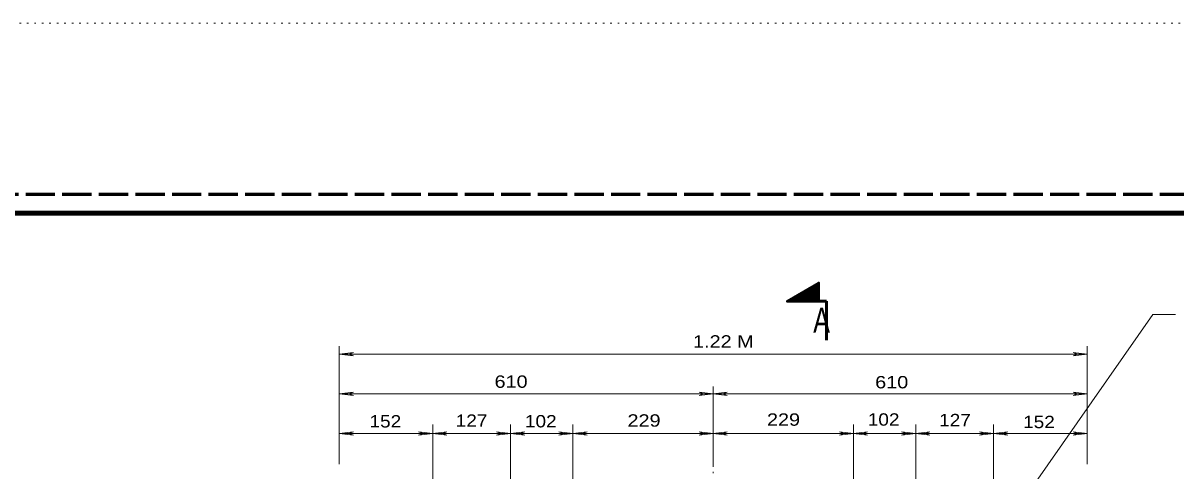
# Model space of a CAD drawing. Extents: x 312583 to 312854, y 144419 to 144597.
# Drawn here: x 312620.3 to 312691.2, y 144569.2 to 144596.8 of the extents above; entities that cross this region are included whole.
import ezdxf
from ezdxf.enums import TextEntityAlignment as Align

# ---------------------------------------------------------------- set-up
doc = ezdxf.new("R2010")
doc.units = 0
doc.header["$LTSCALE"] = 0.3
doc.linetypes.add('DOTTED', pattern=[1.5, 0.3, -1.2])
doc.linetypes.add('LONG_DASHED', pattern=[7.5, 6, -1.5])
for name, color, linetype, lineweight in [('1', 7, 'Continuous', 25), ('2', 7, 'Continuous', 13), ('63', 7, 'DOTTED', 13)]:
    doc.layers.add(name, color=color, linetype=linetype, lineweight=lineweight)

msp = doc.modelspace()

# ---------------------------------------------------------------- linework, layer by layer
at = {"layer": '1', "linetype": 'LONG_DASHED', "lineweight": 60}
msp.add_line((312851.75, 144586.2246), (312583.526, 144586.2246), dxfattribs=at)
at = {"layer": '1', "lineweight": 35}
for p, q in [((312668.867, 144579.6636), (312668.476, 144580.3383)), ((312668.8977, 144579.6636), (312668.499, 144580.3536)), ((312668.9284, 144579.6636), (312668.522, 144580.369)), ((312668.9514, 144579.6636), (312668.545, 144580.3766)), ((312668.982, 144579.6636), (312668.5604, 144580.392)), ((312669.0127, 144579.6636), (312668.5834, 144580.4073)), ((312669.0357, 144579.6713), (312668.6064, 144580.415)), ((312669.0664, 144579.6713), (312668.6217, 144580.4303)), ((312669.0894, 144579.6636), (312668.6447, 144580.438)), ((312669.12, 144579.6636), (312668.6677, 144580.4533)), ((312669.143, 144579.6636), (312668.683, 144580.461)), ((312669.1737, 144579.6636), (312668.706, 144580.4763)), ((312669.2044, 144579.6636), (312668.729, 144580.484)), ((312669.2197, 144579.6866), (312668.7444, 144580.4993)), ((312669.2197, 144579.7403), (312668.775, 144580.507)), ((312669.2197, 144579.7786), (312668.7904, 144580.5223)), ((312669.2197, 144579.8323), (312668.8134, 144580.53)), ((312669.2197, 144579.8783), (312668.8364, 144580.5453)), ((312669.2197, 144579.9243), (312668.8517, 144580.5606)), ((312669.2197, 144579.9703), (312668.8747, 144580.5683)), ((312669.2197, 144580.024), (312668.8977, 144580.5836)), ((312669.2197, 144580.07), (312668.913, 144580.599)), ((312669.2197, 144580.116), (312668.936, 144580.6066)), ((312669.2197, 144580.1696), (312668.9514, 144580.622)), ((312669.2197, 144580.2156), (312668.9744, 144580.6296)), ((312669.2197, 144580.2616), (312668.9974, 144580.645)), ((312669.2197, 144580.3153), (312669.0127, 144580.6526)), ((312669.2197, 144580.3613), (312669.0434, 144580.668)), ((312669.2197, 144580.4073), (312669.0587, 144580.6756)), ((312669.2197, 144580.4533), (312669.0817, 144580.691)), ((312669.2197, 144580.507), (312669.1047, 144580.6986)), ((312669.2197, 144580.5453), (312669.12, 144580.714)), ((312669.2197, 144580.599), (312669.143, 144580.7216)), ((312669.2197, 144580.645), (312669.166, 144580.737)), ((312669.2197, 144580.6986), (312669.1814, 144580.7523)), ((312669.2197, 144580.7446), (312669.2044, 144580.76)), ((312667.3184, 144579.6636), (312667.3184, 144579.679)), ((312667.349, 144579.6636), (312667.3414, 144579.6866)), ((312667.3797, 144579.6636), (312667.3567, 144579.702)), ((312667.4027, 144579.6636), (312667.3797, 144579.7096)), ((312667.4334, 144579.6636), (312667.4027, 144579.725)), ((312667.4564, 144579.6636), (312667.418, 144579.7326)), ((312667.487, 144579.6636), (312667.441, 144579.748)), ((312667.5177, 144579.6636), (312667.464, 144579.7556)), ((312667.5484, 144579.6636), (312667.4794, 144579.771)), ((312667.5714, 144579.6636), (312667.5024, 144579.7786)), ((312667.5944, 144579.6636), (312667.5254, 144579.794)), ((312667.625, 144579.6636), (312667.5484, 144579.8016)), ((312667.648, 144579.6636), (312667.5637, 144579.817)), ((312667.6787, 144579.6636), (312667.5867, 144579.8323)), ((312667.7094, 144579.6636), (312667.6097, 144579.84)), ((312667.74, 144579.6636), (312667.625, 144579.8553)), ((312667.763, 144579.6636), (312667.648, 144579.8706)), ((312667.7937, 144579.6636), (312667.671, 144579.8783)), ((312667.8167, 144579.6636), (312667.6864, 144579.8936)), ((312667.8474, 144579.6636), (312667.7094, 144579.9013)), ((312667.878, 144579.6636), (312667.7324, 144579.9166)), ((312667.901, 144579.6636), (312667.7477, 144579.9243)), ((312667.9317, 144579.6636), (312667.7784, 144579.9396)), ((312667.9547, 144579.6636), (312667.7937, 144579.9473)), ((312667.9854, 144579.6636), (312667.8167, 144579.9626)), ((312668.016, 144579.6636), (312667.8397, 144579.9703)), ((312668.039, 144579.6636), (312667.855, 144579.9856)), ((312668.0697, 144579.6636), (312667.878, 144579.9933)), ((312668.0927, 144579.6636), (312667.901, 144580.0086)), ((312668.1234, 144579.6636), (312667.9164, 144580.024)), ((312668.1464, 144579.6636), (312667.9394, 144580.0316)), ((312668.177, 144579.6636), (312667.9624, 144580.047)), ((312668.2077, 144579.6636), (312667.9777, 144580.0623)), ((312668.2384, 144579.6636), (312668.0007, 144580.07)), ((312668.2614, 144579.6636), (312668.0237, 144580.0853)), ((312668.2844, 144579.6636), (312668.0467, 144580.093)), ((312668.315, 144579.6636), (312668.062, 144580.1083)), ((312668.3457, 144579.6636), (312668.085, 144580.116)), ((312668.3687, 144579.6636), (312668.108, 144580.1313)), ((312668.3994, 144579.6636), (312668.1234, 144580.139)), ((312668.43, 144579.6636), (312668.1464, 144580.1543)), ((312668.453, 144579.6636), (312668.1694, 144580.162)), ((312668.4837, 144579.6636), (312668.1847, 144580.1773)), ((312668.5144, 144579.6636), (312668.2077, 144580.185)), ((312668.5374, 144579.6636), (312668.2307, 144580.2003)), ((312668.568, 144579.6713), (312668.246, 144580.2156)), ((312668.591, 144579.6636), (312668.2767, 144580.2233)), ((312668.6217, 144579.6636), (312668.292, 144580.2386)), ((312668.6447, 144579.6636), (312668.315, 144580.2463)), ((312668.6754, 144579.6636), (312668.338, 144580.2616)), ((312668.706, 144579.6636), (312668.3534, 144580.2693)), ((312668.7367, 144579.6636), (312668.3764, 144580.2846)), ((312668.7597, 144579.6636), (312668.3994, 144580.2923)), ((312668.7827, 144579.6636), (312668.4147, 144580.3076)), ((312668.8134, 144579.6713), (312668.4377, 144580.3153)), ((312668.844, 144579.6636), (312668.4607, 144580.3306))]:
    msp.add_line(p, q, dxfattribs=at)
at = {"layer": '1', "lineweight": 53}
for p in [(312669.2197, 144579.6636), (312669.695, 144577.2716)]:
    msp.add_line(p, (312669.695, 144579.6636), dxfattribs=at)
at = {"layer": '1', "lineweight": 158}
msp.add_lwpolyline([(312616.5, 144423.1446), (312616.5, 144585.0846), (312849, 144585.0846)], dxfattribs=at)
at = {"layer": '1', "lineweight": 53}
msp.add_lwpolyline([(312669.2197, 144579.6636), (312669.2197, 144580.7753), (312667.303, 144579.6636)], close=True, dxfattribs=at)
at = {"layer": '2'}
for p, q in [((312639.7337, 144569.628), (312639.7337, 144576.8883)), ((312685.7337, 144569.628), (312685.7337, 144576.8883)), ((312639.7337, 144576.3976), (312640.6, 144576.505)), ((312639.7337, 144576.3976), (312685.7337, 144576.3976)), ((312639.7337, 144576.3976), (312640.6, 144576.2903)), ((312640.6, 144576.505), (312640.324, 144576.3976)), ((312640.6, 144576.2903), (312640.324, 144576.3976)), ((312684.8674, 144576.505), (312685.1434, 144576.3976)), ((312685.7337, 144576.3976), (312684.8674, 144576.505)), ((312684.8674, 144576.2903), (312685.1434, 144576.3976)), ((312685.7337, 144576.3976), (312684.8674, 144576.2903)), ((312639.7337, 144573.9596), (312640.6, 144574.067)), ((312639.7337, 144573.9596), (312640.6, 144573.8523)), ((312640.6, 144574.067), (312640.324, 144573.9596)), ((312640.6, 144573.8523), (312640.324, 144573.9596)), ((312661.8674, 144574.067), (312662.1434, 144573.9596)), ((312662.7337, 144573.9596), (312661.8674, 144574.067)), ((312661.8674, 144573.8523), (312662.1434, 144573.9596)), ((312662.7337, 144573.9596), (312661.8674, 144573.8523)), ((312662.7337, 144569.4746), (312662.7337, 144574.4043)), ((312662.7337, 144573.9596), (312663.6, 144574.067)), ((312662.7337, 144573.9596), (312663.6, 144573.8523)), ((312663.6, 144574.067), (312663.324, 144573.9596)), ((312663.6, 144573.8523), (312663.324, 144573.9596)), ((312684.8674, 144574.067), (312685.1434, 144573.9596)), ((312685.7337, 144573.9596), (312684.8674, 144574.067)), ((312684.8674, 144573.8523), (312685.1434, 144573.9596)), ((312685.7337, 144573.9596), (312684.8674, 144573.8523)), ((312645.4837, 144566.5843), (312645.4837, 144572.0813)), ((312650.2754, 144567.972), (312650.2754, 144572.0813)), ((312654.1087, 144566.5843), (312654.1087, 144572.0813)), ((312671.3587, 144566.5843), (312671.3587, 144572.0813)), ((312675.192, 144567.972), (312675.192, 144572.0813)), ((312679.9837, 144567.972), (312679.9837, 144572.0813)), ((312639.7337, 144571.5216), (312640.6, 144571.629)), ((312639.7337, 144571.5216), (312640.6, 144571.4143)), ((312640.6, 144571.629), (312640.324, 144571.5216)), ((312640.6, 144571.4143), (312640.324, 144571.5216)), ((312644.6174, 144571.629), (312644.8934, 144571.5216)), ((312645.4837, 144571.5216), (312644.6174, 144571.629)), ((312644.6174, 144571.4143), (312644.8934, 144571.5216)), ((312645.4837, 144571.5216), (312644.6174, 144571.4143)), ((312645.4837, 144571.5216), (312646.35, 144571.629)), ((312645.4837, 144571.5216), (312646.35, 144571.4143)), ((312646.35, 144571.629), (312646.074, 144571.5216)), ((312646.35, 144571.4143), (312646.074, 144571.5216)), ((312649.409, 144571.629), (312649.685, 144571.5216)), ((312650.2754, 144571.5216), (312649.409, 144571.629)), ((312649.409, 144571.4143), (312649.685, 144571.5216)), ((312650.2754, 144571.5216), (312649.409, 144571.4143)), ((312650.2754, 144571.5216), (312651.1417, 144571.629)), ((312650.2754, 144571.5216), (312651.1417, 144571.4143)), ((312651.1417, 144571.629), (312650.8657, 144571.5216)), ((312651.1417, 144571.4143), (312650.8657, 144571.5216)), ((312653.2424, 144571.629), (312653.5184, 144571.5216)), ((312654.1087, 144571.5216), (312653.2424, 144571.629)), ((312653.2424, 144571.4143), (312653.5184, 144571.5216)), ((312654.1087, 144571.5216), (312653.2424, 144571.4143)), ((312654.1087, 144571.5216), (312654.975, 144571.629)), ((312654.1087, 144571.5216), (312654.975, 144571.4143)), ((312654.975, 144571.629), (312654.699, 144571.5216)), ((312654.975, 144571.4143), (312654.699, 144571.5216)), ((312661.8674, 144571.629), (312662.1434, 144571.5216)), ((312662.7337, 144571.5216), (312661.8674, 144571.629)), ((312661.8674, 144571.4143), (312662.1434, 144571.5216)), ((312662.7337, 144571.5216), (312661.8674, 144571.4143)), ((312662.7337, 144571.5216), (312663.6, 144571.629)), ((312662.7337, 144571.5216), (312663.6, 144571.4143)), ((312663.6, 144571.629), (312663.324, 144571.5216)), ((312663.6, 144571.4143), (312663.324, 144571.5216)), ((312670.4924, 144571.629), (312670.7684, 144571.5216)), ((312671.3587, 144571.5216), (312670.4924, 144571.629)), ((312670.4924, 144571.4143), (312670.7684, 144571.5216)), ((312671.3587, 144571.5216), (312670.4924, 144571.4143)), ((312671.3587, 144571.5216), (312672.225, 144571.629)), ((312671.3587, 144571.5216), (312672.225, 144571.4143)), ((312672.225, 144571.629), (312671.949, 144571.5216)), ((312672.225, 144571.4143), (312671.949, 144571.5216)), ((312674.3257, 144571.629), (312674.6017, 144571.5216)), ((312675.192, 144571.5216), (312674.3257, 144571.629)), ((312674.3257, 144571.4143), (312674.6017, 144571.5216)), ((312675.192, 144571.5216), (312674.3257, 144571.4143)), ((312675.192, 144571.5216), (312676.0584, 144571.629)), ((312675.192, 144571.5216), (312676.0584, 144571.4143)), ((312676.0584, 144571.629), (312675.7824, 144571.5216)), ((312676.0584, 144571.4143), (312675.7824, 144571.5216)), ((312679.1174, 144571.629), (312679.3934, 144571.5216)), ((312679.9837, 144571.5216), (312679.1174, 144571.629)), ((312679.1174, 144571.4143), (312679.3934, 144571.5216)), ((312679.9837, 144571.5216), (312679.1174, 144571.4143)), ((312679.9837, 144571.5216), (312680.85, 144571.629)), ((312679.9837, 144571.5216), (312680.85, 144571.4143)), ((312680.85, 144571.629), (312680.574, 144571.5216)), ((312680.85, 144571.4143), (312680.574, 144571.5216)), ((312684.8674, 144571.629), (312685.1434, 144571.5216)), ((312685.7337, 144571.5216), (312684.8674, 144571.629)), ((312684.8674, 144571.4143), (312685.1434, 144571.5216)), ((312685.7337, 144571.5216), (312684.8674, 144571.4143))]:
    msp.add_line(p, q, dxfattribs=at)
at = {"layer": '2', "linetype": 'DOTTED'}
msp.add_line((312662.7337, 144555.7283), (312662.7337, 144569.4746), dxfattribs=at)
at = {"layer": '2'}
for points in [[(312691.1767, 144578.8348), (312689.7781, 144578.8348), (312678.6574, 144562.9273)], [(312639.7337, 144573.9596), (312662.7337, 144573.9596), (312685.7337, 144573.9596)], [(312639.7337, 144571.5216), (312645.4837, 144571.5216), (312650.2754, 144571.5216), (312654.1087, 144571.5216)], [(312654.1087, 144571.5216), (312662.7337, 144571.5216), (312671.3587, 144571.5216)], [(312671.3587, 144571.5216), (312675.192, 144571.5216), (312679.9837, 144571.5216), (312685.7337, 144571.5216)]]:
    msp.add_lwpolyline(points, dxfattribs=at)
at = {"layer": '63'}
msp.add_line((312601.2, 144596.7846), (312853.5, 144596.7846), dxfattribs=at)

# ---------------------------------------------------------------- texts
at = {"layer": '1', "width": 0.75}
msp.add_text('A', height=1.533, dxfattribs=at).set_placement((312669.3999, 144577.7316), align=Align.CENTER)
at = {"layer": '2'}
for s, width, p in [('1.22 M', 1.2, (312661.4966, 144576.8068)), ('610 ', 1.2, (312649.2845, 144574.3334)), ('610 ', 1.2, (312672.6952, 144574.2979)), ('152 ', 1.15, (312641.5938, 144571.8907)), ('127 ', 1.15, (312646.896, 144571.9309)), ('102 ', 1.15, (312651.1534, 144571.8954)), ('229 ', 1.2, (312657.4621, 144571.9406)), ('229 ', 1.2, (312666.0416, 144571.9972)), ('102 ', 1.15, (312672.2407, 144572.0017)), ('127 ', 1.15, (312676.6308, 144571.9662)), ('152 ', 1.15, (312681.794, 144571.8486))]:
    msp.add_text(s, height=0.76, dxfattribs=dict(at, width=width)).set_placement(p)

doc.saveas('drawing.dxf')
